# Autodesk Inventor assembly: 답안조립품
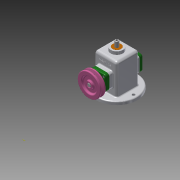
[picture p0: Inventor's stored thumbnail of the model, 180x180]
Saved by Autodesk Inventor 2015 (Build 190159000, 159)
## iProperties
Created: 2021-08
Part Number: 답안조립품
Document SubType Name: Assembly
Designer: 104-1
Author: 104-1
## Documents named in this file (16)
- C:\Users\104-1\Desktop\710806V1031\답안조립품.iam
- C:\Users\104-1\Desktop\710806V1031\V벨트풀리.ipt
- C:\Users\104-1\Desktop\710806V1031\고정핀 1.2x8.ipt
- C:\Users\104-1\Desktop\710806V1031\뒤커버.ipt
- C:\Users\104-1\Desktop\710806V1031\링크.ipt
- C:\Users\104-1\Desktop\710806V1031\멈춤나사 M3x8.ipt
- C:\Users\104-1\Desktop\710806V1031\베어링 12x32x10.ipt
- C:\Users\104-1\Desktop\710806V1031\본체.ipt
- C:\Users\104-1\Desktop\710806V1031\볼트 M4.ipt
- C:\Users\104-1\Desktop\710806V1031\부시.ipt
- C:\Users\104-1\Desktop\710806V1031\슬라이드.ipt
- C:\Users\104-1\Desktop\710806V1031\앞커버.ipt
- C:\Users\104-1\Desktop\710806V1031\오일 실 12 25 7.ipt
- C:\Users\104-1\Desktop\710806V1031\키 4x4x10.ipt
- C:\Users\104-1\Desktop\710806V1031\편심축.ipt
- C:\Users\104-1\Desktop\710806V1031\핀 5x18.ipt
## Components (3 placed, 3 different names)
1. V벨트풀리:1 — 각도:2, 플러쉬:3
2. 고정핀 1.2x8:1
3. 핀 5x18:1 — 플러쉬:1
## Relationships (3: Flush 2, Angle 1)
- 플러쉬:1 [Flush]: 핀 5x18:1
- 각도:2 [Angle]: V벨트풀리:1
- 플러쉬:3 [Flush]: V벨트풀리:1
